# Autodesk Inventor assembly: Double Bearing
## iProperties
Shininess: 64.0
Length Units: 11269
Angle Units: 11279
Time Units: 11290
Mass Units: 11283
Length Display Precision: 3
Angle Display Precision: 2
Created: 2002-02
Part Number: Double Bearing
Document SubType Name: Assembly
Designer: ***
Density: 0.0
Volumn: 0.0
Area: 0.0
PropertySet Name: Model Information
Control State: 0
Master: False
Checked Out: False
Author: ***
